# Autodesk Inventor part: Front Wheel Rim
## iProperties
Shininess: 72.0
Angle Display Precision: 2
Document Length Units: 11269
Document Angle Units: 11279
Document Time Units: 11290
Document Mass Units: 11283
Document Length Units Precision: 3
Document Angle Units Precision: 2
Compacted: True
Created: 2001-08
Part Number: Front Wheel Rim
Document SubType Name: Modeling
Designer: Martin Budgell
Density: 0.0
Volumn: 0.0
Area: 0.0
PropertySet Name: Model Information
Control State: 0
Master: False
Checked Out: False
Author: Martin Budgell
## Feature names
1. Revolution1
2. Revolution2
3. Fillet1
4. Circular Pattern1
5. Revolution3
6. Fillet2
7. Fillet3
8. Fillet4
9. Extrusion1
10. Fillet5
11. Chamfer1
12. Extrusion2
13. Extrusion3
14. Extrusion4
